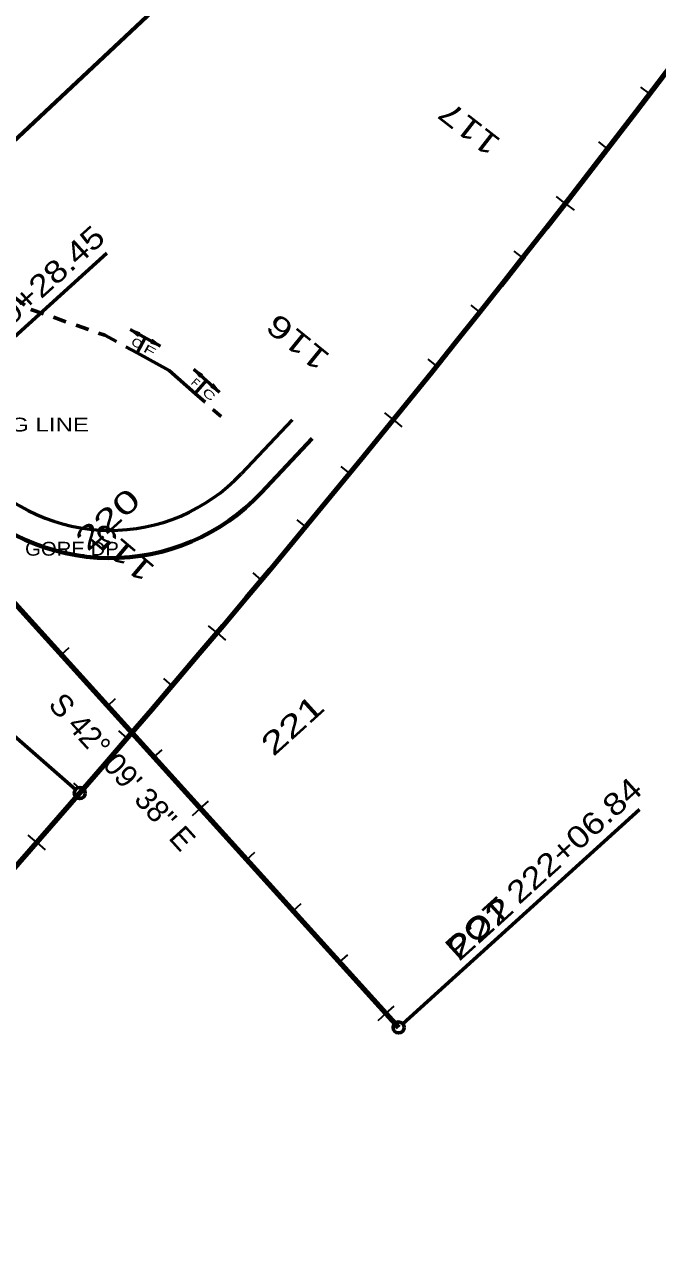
# Model space of a CAD drawing. Extents: x 2717836 to 2719883, y 337327 to 339813.
# Drawn here: x 2719054.1 to 2719283, y 337871.3 to 338313.3 of the extents above; entities that cross this region are included whole.
import ezdxf
from ezdxf.enums import TextEntityAlignment as Align

# ---------------------------------------------------------------- set-up
doc = ezdxf.new("R2010")
doc.units = 0
doc.header["$LTSCALE"] = 3.2
doc.linetypes.add('LONG_DASHED', pattern=[7.5, 6, -1.5])
doc.linetypes.add('SHORT_DASHED', pattern=[2.7, 1.5, -1.2])
for name, color, linetype, lineweight in [('1', 7, 'Continuous', 106), ('22', 7, 'SHORT_DASHED', 60), ('23', 7, 'Continuous', 70), ('3', 7, 'Continuous', 70), ('31', 7, 'Continuous', 35), ('52', 7, 'Continuous', 53), ('6', 7, 'Continuous', 53), ('60', 7, 'Continuous', 13), ('61', 7, 'Continuous', 13)]:
    doc.layers.add(name, color=color, linetype=linetype, lineweight=lineweight)

msp = doc.modelspace()

# ---------------------------------------------------------------- hatches: boundary and pattern name
at = {"layer": '52'}
for points in [[(2719092.243, 338202.949), (2719095.693, 338201.752), (2719094.612, 338201.649), (2719095.102, 338200.671)], [(2719103.21, 338196.952), (2719099.76, 338198.148), (2719100.841, 338198.251), (2719100.351, 338199.229)], [(2719115.252, 338188.651), (2719118.346, 338186.711), (2719117.269, 338186.853), (2719117.528, 338185.79)], [(2719124.594, 338180.346), (2719121.5, 338182.286), (2719122.577, 338182.144), (2719122.319, 338183.207)]]:
    msp.add_hatch(color=256, dxfattribs=at).paths.add_polyline_path(points)

# ---------------------------------------------------------------- linework, layer by layer
at = {"layer": '1'}
for p, q in [((2719002.473, 338156.897), (2719189.327, 337950.539)), ((2718598.813, 337489.479), (2719074.059, 338035.314))]:
    msp.add_line(p, q, dxfattribs=at)
msp.add_arc((2715303.107, 341318.594), 5000, 318.95467, 328.67947, dxfattribs=at)
at = {"layer": '22'}
for p, q in [((2719056.377, 338210.214), (2719083.159, 338200.888)), ((2719083.159, 338200.888), (2719094.767, 338194.537)), ((2719115.77, 338179.829), (2719125.164, 338171.472))]:
    msp.add_line(p, q, dxfattribs=at)
msp.add_lwpolyline([(2719015.923, 338239.196), (2719036.374, 338224.824), (2719056.377, 338210.214)], dxfattribs=at)
at = {"layer": '22', "linetype": 'LONG_DASHED'}
msp.add_lwpolyline([(2719094.767, 338194.537), (2719106.376, 338188.185), (2719115.77, 338179.829)], dxfattribs=at)
at = {"layer": '23'}
msp.add_line((2719374.169, 338574.501), (2718990.259, 338215.014), dxfattribs=at)
msp.add_arc((2718932.366, 337992.345), 585.751, 113.27176, 113.27176, dxfattribs=at)
at = {"layer": '3'}
msp.add_line((2719158.122, 338163.486), (2719139.67, 338143.888), dxfattribs=at)
msp.add_arc((2719085.065, 338195.301), 75, 222.16044, 316.72468, dxfattribs=at)
at = {"layer": '31'}
for p, q in [((2719280.124, 338288.192), (2719276.943, 338290.616)), ((2719264.923, 338268.345), (2719261.753, 338270.785)), ((2719249.622, 338248.574), (2719246.465, 338251.03)), ((2719249.622, 338248.574), (2719252.779, 338246.118)), ((2719234.223, 338228.88), (2719231.078, 338231.351)), ((2719218.725, 338209.263), (2719215.593, 338211.75)), ((2719203.129, 338189.724), (2719200.009, 338192.227)), ((2719187.436, 338170.263), (2719184.329, 338172.781)), ((2719187.436, 338170.263), (2719190.544, 338167.744)), ((2719171.646, 338150.88), (2719168.551, 338153.415)), ((2719155.759, 338131.577), (2719152.677, 338134.127)), ((2719139.776, 338112.354), (2719136.707, 338114.919)), ((2719123.697, 338093.211), (2719120.641, 338095.791)), ((2719123.697, 338093.211), (2719126.754, 338090.631)), ((2719067.276, 338085.329), (2719070.241, 338088.014)), ((2719107.523, 338074.148), (2719104.479, 338076.744)), ((2719084.057, 338066.797), (2719087.022, 338069.482)), ((2719091.253, 338055.167), (2719088.222, 338057.778)), ((2719100.837, 338048.266), (2719103.802, 338050.95)), ((2719074.888, 338036.267), (2719071.871, 338038.893)), ((2719117.617, 338029.734), (2719120.582, 338032.419)), ((2719117.617, 338029.734), (2719114.652, 338027.049)), ((2719058.472, 338017.412), (2719055.455, 338020.039)), ((2719058.472, 338017.412), (2719061.489, 338014.786)), ((2719134.397, 338011.202), (2719137.362, 338013.887)), ((2719151.177, 337992.671), (2719154.143, 337995.355)), ((2719167.958, 337974.139), (2719170.923, 337976.824)), ((2719184.738, 337955.607), (2719181.773, 337952.922)), ((2719184.738, 337955.607), (2719187.703, 337958.292))]:
    msp.add_line(p, q, dxfattribs=at)
at = {"layer": '31', "lineweight": 60}
for p, q in [((2719003.955, 338158.239), (2719083.848, 338230.581)), ((2719072.55, 338036.627), (2718991.882, 338106.863)), ((2719190.81, 337951.881), (2719276.446, 338029.424))]:
    msp.add_line(p, q, dxfattribs=at)
for centre in [(2719074.059, 338035.314), (2719189.327, 337950.539)]:
    msp.add_circle(centre, 2, dxfattribs=at)
at = {"layer": '52'}
for p, q in [((2719092.243, 338202.949), (2719103.21, 338196.952)), ((2719097.726, 338199.95), (2719094.767, 338194.537)), ((2719115.252, 338188.651), (2719124.594, 338180.346)), ((2719115.77, 338179.829), (2719119.923, 338184.499))]:
    msp.add_line(p, q, dxfattribs=at)
at = {"layer": '52', "lineweight": 25}
for points in [[(2719092.243, 338202.949), (2719095.693, 338201.752), (2719094.612, 338201.649), (2719095.102, 338200.671)], [(2719103.21, 338196.952), (2719099.76, 338198.148), (2719100.841, 338198.251), (2719100.351, 338199.229)], [(2719115.252, 338188.651), (2719118.346, 338186.711), (2719117.269, 338186.853), (2719117.528, 338185.79)], [(2719124.594, 338180.346), (2719121.5, 338182.286), (2719122.577, 338182.144), (2719122.319, 338183.207)]]:
    msp.add_lwpolyline(points, close=True, dxfattribs=at)
at = {"layer": '6'}
msp.add_line((2719150.842, 338170.341), (2719132.389, 338150.743), dxfattribs=at)
msp.add_arc((2719085.065, 338195.301), 65, 222.16044, 316.72468, dxfattribs=at)

# ---------------------------------------------------------------- texts
at = {"layer": '31'}
for s, rotation, width, p in [('117', 142.12, 1.35, (2719226.82, 338271.379)), ('PT 219+28.45', 42.16, 1.2, (2719023.844, 338180.97)), ('116', 140.975, 1.4, (2719165.095, 338193.519)), ('220', 42.16, 1.5, (2719076.902, 338122.374)), ('115', 139.829, 1.45, (2719101.826, 338116.91)), ('221', 42.16, 1.45, (2719144.022, 338048.248)), ('POT 222+06.84', 42.16, 1.2, (2719210.698, 337974.612)), ('222', 42.16, 1.55, (2719211.143, 337974.121))]:
    msp.add_text(s, height=8, rotation=rotation, dxfattribs=dict(at, width=width)).set_placement(p)
msp.add_text('S 42° 09\' 38" E', height=8, rotation=312.16, dxfattribs=at).set_placement((2719086.471, 338040.294), align=Align.CENTER)
at = {"layer": '52'}
for s, rotation, width, p in [('C', 331.335, 1.3, (2719093.935, 338196.756)), ('F', 331.335, 1.75, (2719098.632, 338194.113)), ('C', 318.345, 1.65, (2719119.793, 338178.35))]:
    msp.add_text(s, height=3, rotation=rotation, dxfattribs=dict(at, width=width)).set_placement(p, align=Align.CENTER)
msp.add_text('F', height=3, rotation=318.345, dxfattribs=at).set_placement((2719114.923, 338182.607), align=Align.CENTER)
at = {"layer": '60', "width": 1.1}
msp.add_text('GORE DP', height=5, dxfattribs=at).set_placement((2719054.276, 338121.173))
at = {"layer": '61', "width": 1.3}
msp.add_text('BREAKING LINE ', height=5, dxfattribs=at).set_placement((2719010.723, 338166.075))

doc.saveas('drawing.dxf')
